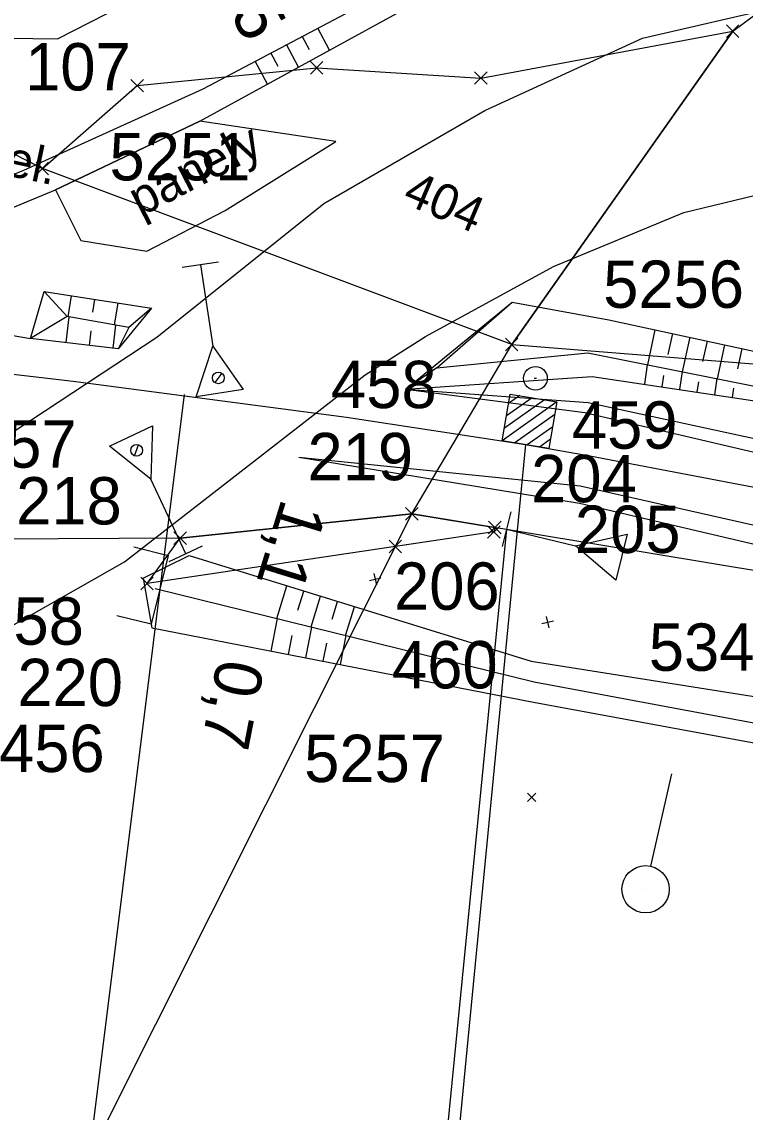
# Model space of a CAD drawing. Extents: x -804899 to -803847, y -1165742 to -1164942.
# Drawn here: x -804771.96 to -804741.39, y -1165146.47 to -1165100.4 of the extents above; entities that cross this region are included whole.
import ezdxf

# ---------------------------------------------------------------- set-up
doc = ezdxf.new("R2010")
doc.units = 0
for name, color, linetype in [('0381KM061-064P - Vrstva 1', 7, 'Continuous'), ('0381KM061-064P - Vrstva 16', 7, 'Continuous'), ('0381KM061-064P - Vrstva 27', 7, 'Continuous'), ('0381KM061-064P - Vrstva 3', 7, 'Continuous'), ('0381KM061-064P - Vrstva 36', 7, 'Continuous'), ('0381KM061-064P - Vrstva 4', 7, 'Continuous'), ('0381KM061-064P - Vrstva 43', 7, 'Continuous'), ('0381KM061-064P - Vrstva 48', 7, 'Continuous'), ('0381KM061-064P - Vrstva 49', 7, 'Continuous'), ('0381KM061-064P - Vrstva 51', 7, 'Continuous'), ('0381KM061-064P - Vrstva 55', 7, 'Continuous'), ('0381KM061-064P - Vrstva 57', 7, 'Continuous'), ('0381KM061-064P - Vrstva 8', 7, 'Continuous'), ('DZ - DZ_krizek', 7, 'Continuous'), ('DZ - DZ_ostat', 7, 'Continuous'), ('DZ - DZ_číslo', 7, 'Continuous'), ('szdc - hran DP', 7, 'Continuous'), ('szdc - szdc_cislo', 7, 'Continuous'), ('szdc - szdc_krizek', 7, 'Continuous'), ('TZ - TZ_cislo', 7, 'Continuous'), ('VB - VB', 7, 'Continuous'), ('VB - VB_cislo', 7, 'Continuous'), ('VB - VB_krizek', 7, 'Continuous')]:
    doc.layers.add(name, color=color, linetype=linetype)

msp = doc.modelspace()

# ---------------------------------------------------------------- linework, layer by layer
at = {"layer": '0381KM061-064P - Vrstva 1'}
for points in [[(-804783.453, -1165113.99), (-804769.784, -1165115.585), (-804758.243, -1165117.11), (-804750.67, -1165118.27), (-804748.021, -1165118.722)], [(-804748.021, -1165118.722), (-804737.69, -1165120.695), (-804722.056, -1165124.431), (-804702.108, -1165130.565), (-804682.19, -1165138.236), (-804666.439, -1165145.5)]]:
    msp.add_lwpolyline(points, dxfattribs=at)
at = {"layer": '0381KM061-064P - Vrstva 16'}
msp.add_lwpolyline([(-804770.535, -1165107.501), (-804769.468, -1165109.647), (-804766.68, -1165110.089), (-804763.361, -1165108.378), (-804758.689, -1165105.46), (-804764.444, -1165104.598), (-804770.535, -1165107.501)], dxfattribs=at)
at = {"layer": '0381KM061-064P - Vrstva 27'}
msp.add_line((-804750.306, -1165115.467), (-804750.206, -1165115.467), dxfattribs=at)
msp.add_circle((-804750.256, -1165115.467), 0.5, dxfattribs=at)
at = {"layer": '0381KM061-064P - Vrstva 3'}
for p, q in [((-804749.348, -1165116.467), (-804751.656, -1165118.102)), ((-804749.87, -1165116.378), (-804751.567, -1165117.579)), ((-804750.394, -1165116.288), (-804751.477, -1165117.056)), ((-804750.916, -1165116.199), (-804751.388, -1165116.533)), ((-804749.437, -1165116.989), (-804751.133, -1165118.191)), ((-804749.526, -1165117.513), (-804750.61, -1165118.28)), ((-804749.615, -1165118.035), (-804750.087, -1165118.369))]:
    msp.add_line(p, q, dxfattribs=at)
msp.add_lwpolyline([(-804749.684, -1165118.438), (-804751.656, -1165118.102), (-804751.319, -1165116.13), (-804749.348, -1165116.467)], close=True, dxfattribs=at)
msp.add_lwpolyline([(-804750.67, -1165118.27), (-804753.547, -1165147.904), (-804748.478, -1165148.388), (-804749.734, -1165164.119)], dxfattribs=at)
at = {"layer": '0381KM061-064P - Vrstva 36'}
for p, q in [((-804745.38, -1165136.083), (-804744.493, -1165132.183)), ((-804745.602, -1165137.058), (-804745.602, -1165137.058))]:
    msp.add_line(p, q, dxfattribs=at)
msp.add_circle((-804745.602, -1165137.058), 1, dxfattribs=at)
at = {"layer": '0381KM061-064P - Vrstva 4'}
for p, q in [((-804763.642, -1165110.553), (-804765.182, -1165110.783)), ((-804763.508, -1165115.254), (-804763.801, -1165115.646)), ((-804769.784, -1165115.585), (-804758.243, -1165117.11)), ((-804765.098, -1165116.15), (-804771.936, -1165170.886)), ((-804767.194, -1165118.739), (-804767.025, -1165118.28)), ((-804765.729, -1165123.208), (-804764.319, -1165122.55))]:
    msp.add_line(p, q, dxfattribs=at)
for points in [[(-804843.833, -1165105.728), (-804840.797, -1165106.06), (-804819.65, -1165108.38), (-804802.702, -1165110.303), (-804779.709, -1165112.392), (-804771.588, -1165113.785)], [(-804764.412, -1165110.668), (-804763.89, -1165114.106), (-804762.613, -1165115.941), (-804764.587, -1165116.247), (-804763.89, -1165114.106)], [(-804755.733, -1165115.927), (-804748.168, -1165116.905), (-804721.253, -1165123.253), (-804698.663, -1165130.219), (-804681.332, -1165136.993), (-804671.473, -1165141.648), (-804648.845, -1165153.359), (-804638.113, -1165160.035), (-804624.479, -1165168.696), (-804602.557, -1165183.067), (-804574.466, -1165201.721), (-804542.719, -1165222.837), (-804507.36, -1165246.549), (-804477.085, -1165266.816), (-804448.754, -1165285.875), (-804421.182, -1165304.145), (-804392.893, -1165323.086), (-804369.849, -1165338.366), (-804348.858, -1165352.041), (-804325.134, -1165367.981), (-804299.324, -1165385.271), (-804266.052, -1165407.314), (-804234.277, -1165428.598)], [(-804755.733, -1165115.927), (-804748.032, -1165116.485), (-804721.047, -1165122.361), (-804698.438, -1165129.771), (-804680.982, -1165136.504), (-804671.213, -1165140.894), (-804648.415, -1165152.455), (-804637.551, -1165159.434), (-804624.035, -1165168.294), (-804602.248, -1165182.377), (-804573.745, -1165201.202), (-804542.465, -1165222.561), (-804507.059, -1165246.026), (-804476.473, -1165266.236), (-804448.309, -1165285.076), (-804421.024, -1165303.102), (-804392.59, -1165322.59), (-804369.414, -1165337.648), (-804348.678, -1165351.592), (-804324.758, -1165367.42), (-804298.904, -1165384.417), (-804265.65, -1165406.497), (-804234.045, -1165428.038)], [(-804765.024, -1165122.879), (-804766.502, -1165119.732), (-804768.248, -1165118.335), (-804766.441, -1165117.481), (-804766.502, -1165119.732)], [(-804760.257, -1165118.798), (-804748.359, -1165120.009), (-804721.794, -1165126.004), (-804699.133, -1165133.383), (-804682.383, -1165139.582), (-804672.624, -1165144.091), (-804650.427, -1165155.704), (-804639.382, -1165162.287), (-804626.131, -1165170.888), (-804604.367, -1165185.52), (-804576.364, -1165204.152)], [(-804760.257, -1165118.798), (-804748.388, -1165120.746), (-804721.772, -1165126.976), (-804699.376, -1165134.382), (-804682.716, -1165140.57), (-804673.684, -1165144.668), (-804650.962, -1165156.638), (-804639.654, -1165163.015), (-804626.635, -1165171.43)]]:
    msp.add_lwpolyline(points, dxfattribs=at)
for centre in [(-804763.655, -1165115.449), (-804767.109, -1165118.51)]:
    msp.add_circle(centre, 0.248, dxfattribs=at)
at = {"layer": '0381KM061-064P - Vrstva 43'}
msp.add_lwpolyline([(-804767.225, -1165122.587), (-804765.769, -1165122.947), (-804766.487, -1165125.859), (-804767.944, -1165125.5)], dxfattribs=at)
at = {"layer": '0381KM061-064P - Vrstva 48'}
for p, q in [((-804758.952, -1165101.6), (-804759.448, -1165100.665)), ((-804759.81, -1165101.582), (-804760.11, -1165101.016)), ((-804761.129, -1165102.294), (-804761.434, -1165101.719)), ((-804760.267, -1165102.318), (-804760.772, -1165101.368)), ((-804761.584, -1165103.037), (-804762.097, -1165102.071)), ((-804770.005, -1165112.865), (-804769.867, -1165111.982)), ((-804768.964, -1165112.678), (-804768.88, -1165112.136)), ((-804768.036, -1165113.213), (-804767.892, -1165112.289)), ((-804769.976, -1165112.871), (-804770.102, -1165113.958)), ((-804768.002, -1165113.219), (-804768.115, -1165114.189)), ((-804769.037, -1165113.456), (-804769.109, -1165114.073)), ((-804745.51, -1165114.894), (-804745.19, -1165113.417)), ((-804744.647, -1165114.455), (-804744.457, -1165113.575)), ((-804744.039, -1165115.188), (-804743.724, -1165113.734)), ((-804743.178, -1165114.758), (-804742.991, -1165113.892)), ((-804742.568, -1165115.482), (-804742.258, -1165114.051)), ((-804741.709, -1165115.061), (-804741.525, -1165114.209)), ((-804745.531, -1165114.89), (-804745.654, -1165115.72)), ((-804744.841, -1165115.354), (-804744.913, -1165115.83)), ((-804744.058, -1165115.184), (-804744.171, -1165115.941)), ((-804742.585, -1165115.478), (-804742.687, -1165116.163)), ((-804743.364, -1165115.619), (-804743.429, -1165116.052)), ((-804741.887, -1165115.885), (-804741.946, -1165116.274)), ((-804761.183, -1165125.614), (-804760.758, -1165124.234)), ((-804760.293, -1165125.257), (-804760.045, -1165124.454)), ((-804759.732, -1165125.971), (-804759.332, -1165124.674)), ((-804758.852, -1165125.648), (-804758.619, -1165124.894)), ((-804758.281, -1165126.329), (-804757.906, -1165125.115)), ((-804761.174, -1165125.616), (-804761.442, -1165126.991)), ((-804759.718, -1165125.975), (-804759.972, -1165127.277)), ((-804760.55, -1165126.331), (-804760.707, -1165127.134)), ((-804758.263, -1165126.334), (-804758.502, -1165127.563)), ((-804759.089, -1165126.661), (-804759.237, -1165127.42))]:
    msp.add_line(p, q, dxfattribs=at)
at = {"layer": '0381KM061-064P - Vrstva 49'}
for p, q in [((-804770.535, -1165107.501), (-804764.444, -1165104.598)), ((-804767.436, -1165113.319), (-804770.041, -1165112.859)), ((-804757.082, -1165123.711), (-804756.968, -1165124.197)), ((-804757.268, -1165124.011), (-804756.782, -1165123.897)), ((-804749.797, -1165125.528), (-804749.683, -1165126.014)), ((-804749.983, -1165125.828), (-804749.497, -1165125.714)), ((-804750.241, -1165133.351), (-804750.595, -1165132.997)), ((-804750.241, -1165132.997), (-804750.595, -1165133.351))]:
    msp.add_line(p, q, dxfattribs=at)
for points in [[(-804782.933, -1165100.952), (-804770.452, -1165101.128), (-804760.766, -1165096.165), (-804750.377, -1165086.376), (-804747.774, -1165080.287)], [(-804778.125, -1165109.25), (-804771.874, -1165106.665), (-804764.298, -1165103.24), (-804757.01, -1165099.37), (-804754.139, -1165096.348)], [(-804764.444, -1165104.598), (-804755.942, -1165099.957), (-804754.139, -1165096.348)], [(-804778.59, -1165110.844), (-804770.535, -1165107.501)], [(-804771.021, -1165111.803), (-804770.041, -1165112.859), (-804771.588, -1165113.785)], [(-804755.733, -1165115.927), (-804751.237, -1165112.247), (-804747.153, -1165112.992), (-804720.555, -1165118.745), (-804697.457, -1165124.856)], [(-804754.423, -1165115.02), (-804751.237, -1165112.247)], [(-804766.482, -1165112.508), (-804767.436, -1165113.319), (-804767.889, -1165114.215)], [(-804754.423, -1165115.02), (-804748.035, -1165114.39), (-804721.192, -1165119.749), (-804697.281, -1165126.544)], [(-804754.423, -1165115.02), (-804755.733, -1165115.927)], [(-804755.733, -1165115.927), (-804747.853, -1165115.391), (-804738.732, -1165116.754), (-804720.925, -1165120.918), (-804697.629, -1165127.819)], [(-804766.835, -1165123.914), (-804764.887, -1165122.959), (-804750.44, -1165127.42), (-804724.293, -1165131.559), (-804700.35, -1165136.808), (-804683.355, -1165141.958), (-804673.479, -1165145.601), (-804651.73, -1165158.215)], [(-804766.835, -1165123.914), (-804766.462, -1165126.013)], [(-804766.318, -1165124.347), (-804750.308, -1165128.296), (-804724.802, -1165133.057), (-804699.443, -1165138.401), (-804683.582, -1165142.5), (-804673.524, -1165146.323), (-804651.73, -1165158.215)], [(-804766.462, -1165126.013), (-804750.339, -1165129.153), (-804724.988, -1165133.826)]]:
    msp.add_lwpolyline(points, dxfattribs=at)
msp.add_lwpolyline([(-804771.588, -1165113.785), (-804771.021, -1165111.803), (-804766.482, -1165112.508), (-804767.889, -1165114.215)], close=True, dxfattribs=at)
at = {"layer": '0381KM061-064P - Vrstva 51'}
for points in [[(-804799.401, -1165124.127), (-804788.787, -1165123.564), (-804781.178, -1165122.085), (-804777.377, -1165120.679), (-804772.772, -1165118.025), (-804766.254, -1165113.723), (-804759.193, -1165108.078), (-804752.39, -1165104.15), (-804745.737, -1165101.091), (-804737.367, -1165099.155), (-804728.561, -1165098.534)], [(-804786.505, -1165130.38), (-804780.047, -1165129.084), (-804774.134, -1165126.908), (-804767.616, -1165123.226), (-804757.446, -1165115.319), (-804754.899, -1165113.701), (-804749.494, -1165110.738), (-804743.99, -1165108.455), (-804736.292, -1165106.603), (-804728.9, -1165105.899)]]:
    msp.add_lwpolyline(points, dxfattribs=at)
at = {"layer": '0381KM061-064P - Vrstva 55'}
msp.add_lwpolyline([(-804834.02, -1165173.21), (-804777.95, -1165165.95), (-804761.65, -1165133.49), (-804755.48, -1165121.19), (-804751.26, -1165114.04), (-804741.92, -1165100.8), (-804736.13, -1165096.49), (-804701.79, -1165069.72), (-804628.296, -1165012.443)], dxfattribs=at)
msp.add_lwpolyline([(-804771.09, -1165106.6), (-804767.08, -1165103.1), (-804759.5, -1165102.35), (-804752.56, -1165102.78), (-804741.92, -1165100.8), (-804751.26, -1165114.04)], close=True, dxfattribs=at)
at = {"layer": '0381KM061-064P - Vrstva 8'}
for p, q in [((-804751.3, -1165121.108), (-804751.658, -1165122.566)), ((-804751.479, -1165121.837), (-804755.655, -1165164.119)), ((-804746.86, -1165123.997), (-804748.565, -1165122.549))]:
    msp.add_line(p, q, dxfattribs=at)
msp.add_lwpolyline([(-804751.479, -1165121.837), (-804748.565, -1165122.549), (-804746.385, -1165122.054), (-804746.86, -1165123.997), (-804748.565, -1165122.549)], dxfattribs=at)
at = {"layer": 'DZ - DZ_krizek'}
for p, q in [((-804755.215, -1165121.455), (-804755.746, -1165120.925)), ((-804755.746, -1165121.455), (-804755.215, -1165120.925)), ((-804751.702, -1165122.037), (-804752.233, -1165121.507)), ((-804752.233, -1165122.037), (-804751.702, -1165121.507)), ((-804765.005, -1165122.485), (-804765.536, -1165121.955)), ((-804765.536, -1165122.485), (-804765.005, -1165121.955)), ((-804751.747, -1165122.224), (-804752.278, -1165121.694)), ((-804752.278, -1165122.224), (-804751.747, -1165121.694)), ((-804755.911, -1165122.842), (-804756.442, -1165122.312)), ((-804756.442, -1165122.842), (-804755.911, -1165122.312)), ((-804766.404, -1165124.399), (-804766.935, -1165123.869)), ((-804766.935, -1165124.399), (-804766.404, -1165123.869))]:
    msp.add_line(p, q, dxfattribs=at)
at = {"layer": 'DZ - DZ_ostat'}
for p, q in [((-804765.27, -1165122.22), (-804755.48, -1165121.19)), ((-804755.48, -1165121.19), (-804751.967, -1165121.772)), ((-804752.012, -1165121.959), (-804766.669, -1165124.134)), ((-804751.967, -1165121.772), (-804752.012, -1165121.959)), ((-804766.669, -1165124.134), (-804765.27, -1165122.22))]:
    msp.add_line(p, q, dxfattribs=at)
msp.add_lwpolyline([(-804751.967, -1165121.772), (-804752.012, -1165121.959), (-804756.176, -1165122.577)], dxfattribs=at)
at = {"layer": 'szdc - hran DP'}
for p, q in [((-804752.56, -1165102.78), (-804741.92, -1165100.8)), ((-804741.92, -1165100.8), (-804751.26, -1165114.04)), ((-804767.08, -1165103.1), (-804759.5, -1165102.35)), ((-804759.5, -1165102.35), (-804752.56, -1165102.78)), ((-804771.09, -1165106.6), (-804767.08, -1165103.1)), ((-804777.08, -1165103.56), (-804771.09, -1165106.6)), ((-804751.26, -1165114.04), (-804735.44, -1165115.31)), ((-804755.48, -1165121.19), (-804765.27, -1165122.22)), ((-804738.35, -1165124.03), (-804755.48, -1165121.19)), ((-804765.27, -1165122.22), (-804781.51, -1165122.32))]:
    msp.add_line(p, q, dxfattribs=at)
at = {"layer": 'szdc - szdc_krizek'}
for p, q in [((-804741.655, -1165101.065), (-804742.186, -1165100.535)), ((-804742.186, -1165101.065), (-804741.655, -1165100.535)), ((-804759.235, -1165102.615), (-804759.766, -1165102.085)), ((-804759.766, -1165102.615), (-804759.235, -1165102.085)), ((-804752.295, -1165103.045), (-804752.826, -1165102.515)), ((-804752.826, -1165103.045), (-804752.295, -1165102.515)), ((-804766.815, -1165103.365), (-804767.346, -1165102.835)), ((-804767.346, -1165103.365), (-804766.815, -1165102.835)), ((-804770.825, -1165106.865), (-804771.356, -1165106.335)), ((-804771.356, -1165106.865), (-804770.825, -1165106.335)), ((-804750.995, -1165114.305), (-804751.526, -1165113.775)), ((-804751.526, -1165114.305), (-804750.995, -1165113.775)), ((-804755.215, -1165121.455), (-804755.746, -1165120.925)), ((-804755.746, -1165121.455), (-804755.215, -1165120.925)), ((-804765.005, -1165122.485), (-804765.536, -1165121.955)), ((-804765.536, -1165122.485), (-804765.005, -1165121.955))]:
    msp.add_line(p, q, dxfattribs=at)
at = {"layer": 'VB - VB'}
msp.add_lwpolyline([(-804766.669, -1165124.134), (-804765.27, -1165122.22), (-804755.48, -1165121.19), (-804751.967, -1165121.772), (-804752.012, -1165121.959)], close=True, dxfattribs=at)
at = {"layer": 'VB - VB_krizek'}
for p, q in [((-804755.215, -1165121.455), (-804755.746, -1165120.925)), ((-804755.746, -1165121.455), (-804755.215, -1165120.925)), ((-804751.702, -1165122.037), (-804752.233, -1165121.507)), ((-804752.233, -1165122.037), (-804751.702, -1165121.507)), ((-804765.005, -1165122.485), (-804765.536, -1165121.955)), ((-804765.536, -1165122.485), (-804765.005, -1165121.955)), ((-804751.747, -1165122.224), (-804752.278, -1165121.694)), ((-804752.278, -1165122.224), (-804751.747, -1165121.694)), ((-804766.404, -1165124.399), (-804766.935, -1165123.869)), ((-804766.935, -1165124.399), (-804766.404, -1165123.869))]:
    msp.add_line(p, q, dxfattribs=at)

# ---------------------------------------------------------------- texts
at = {"layer": '0381KM061-064P - Vrstva 16'}
for s, rotation, p in [('panely', 27.2719, (-804766.953, -1165108.661)), ('panel.', 348.0707, (-804775.996, -1165106.177))]:
    msp.add_text(s, height=1.5, rotation=rotation, dxfattribs=at).set_placement(p)
at = {"layer": '0381KM061-064P - Vrstva 48'}
for s, rotation, p in [('0,5', 297.9687, (-804764.215, -1165098.091)), ('1,1', 252.8402, (-804760.962, -1165120.493)), ('0,7', 258.9794, (-804763.666, -1165127.248))]:
    msp.add_text(s, height=2, rotation=rotation, dxfattribs=at).set_placement(p)
at = {"layer": '0381KM061-064P - Vrstva 57'}
msp.add_text('404', height=1.5, rotation=336.9346, dxfattribs=at).set_placement((-804755.929, -1165108.038))
at = {"layer": 'DZ - DZ_číslo'}
for s, p in [('219', (-804759.887, -1165119.772)), ('204', (-804750.439, -1165120.702)), ('218', (-804772.198, -1165121.641)), ('205', (-804748.588, -1165122.845)), ('206', (-804756.231, -1165125.246)), ('220', (-804772.146, -1165129.316))]:
    msp.add_text(s, height=2, dxfattribs=at).set_placement(p)
at = {"layer": 'szdc - szdc_cislo'}
for s, p in [('5251', (-804768.255, -1165107.102)), ('5256', (-804747.393, -1165112.489)), ('5258', (-804775.286, -1165126.722)), ('5341', (-804745.465, -1165127.824)), ('5257', (-804760.028, -1165132.526))]:
    msp.add_text(s, height=2, dxfattribs=at).set_placement(p)
at = {"layer": 'TZ - TZ_cislo'}
msp.add_text('107', height=2, dxfattribs=at).set_placement((-804771.82, -1165103.305))
at = {"layer": 'VB - VB_cislo'}
for s, p in [('458', (-804758.893, -1165116.726)), ('459', (-804748.714, -1165118.44)), ('457', (-804774.109, -1165119.241)), ('460', (-804756.315, -1165128.568)), ('456', (-804772.921, -1165132.103))]:
    msp.add_text(s, height=2, dxfattribs=at).set_placement(p)

doc.saveas('drawing.dxf')
